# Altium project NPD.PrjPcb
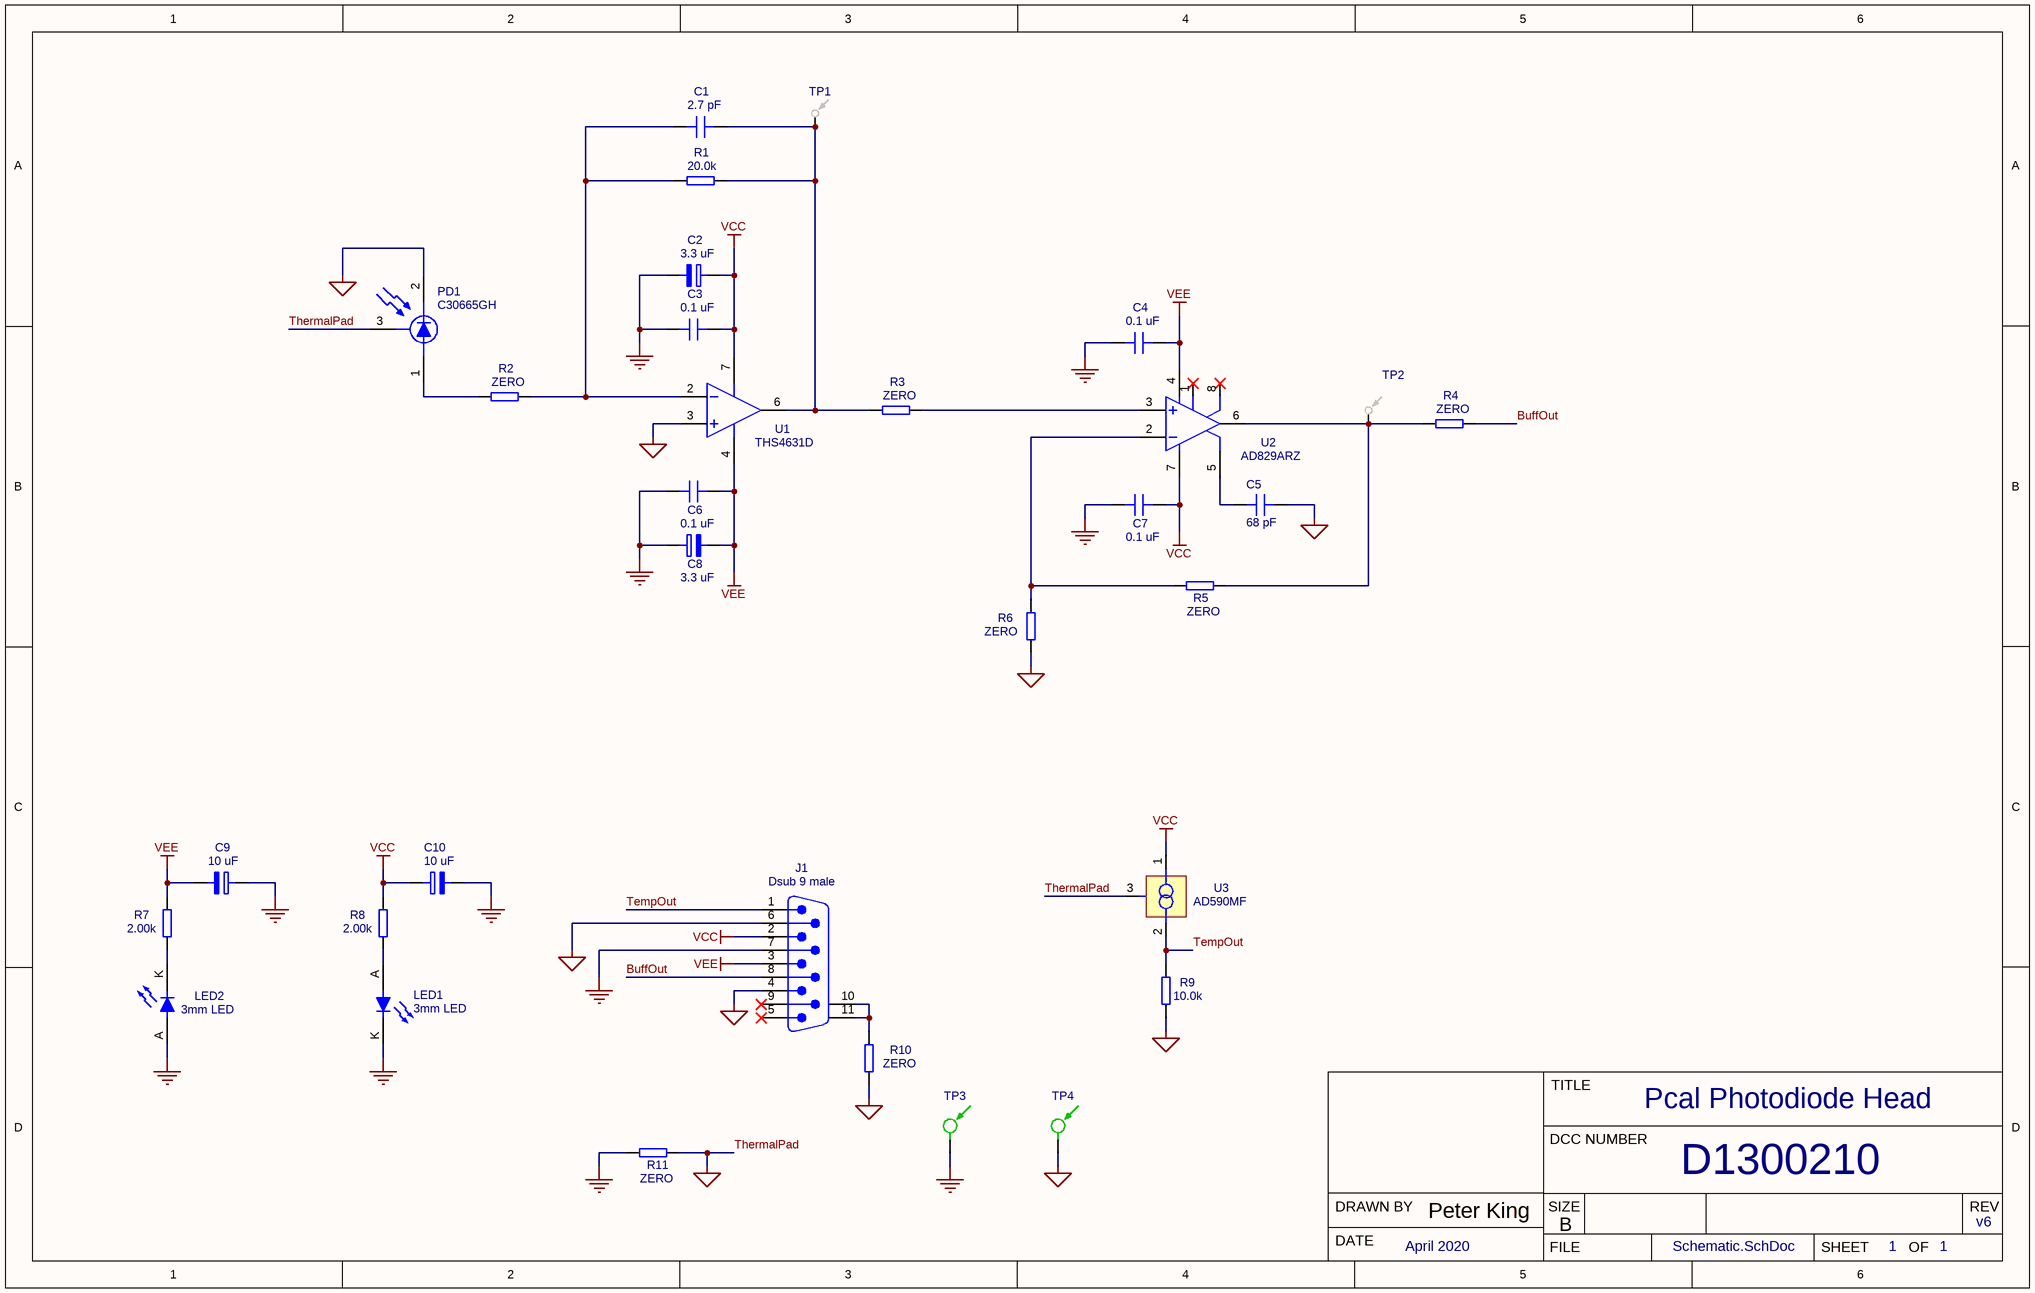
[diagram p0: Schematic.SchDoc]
1 sheet, 32 parts. Net scope: global (net labels, ports and power ports of the same name join across sheets).
Board file: NPD.PcbDoc

## Sheet Schematic.SchDoc
size B; Organization: Altium Limited; Address1: 3 Minna Close; Address2: Belrose; Address3: NSW 2085; Address4: Australia; PageSetup: Record=PageOptions|CenterHorizontal=True|CenterVertical=True|PrintScale=1.12|XCorrection=1.00|YCorrection=1.00|PrintKind=2|BorderSize=5000000|LeftOffset=0|BottomOffset=0|Orientation=2|PaperLength=1000|PaperWidth=1000|Scale=100|PaperSource=15|PrintQuality=600|MediaType=1|DitherType=10|PaperKind=Tabloid|PrintScaleMode=1

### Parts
C1  2.7 pF  [Kemet 0805, low density]
C2  3.3 uF  [Kemet 3528-21]
C3  0.1 uF  [Kemet EIA 1206]
C4  0.1 uF  [0805 low density]
C5  68 pF  [Kemet EIA 0805]
C6  0.1 uF  [Kemet EIA 1206]
C7  0.1 uF  [0805 low density]
C8  3.3 uF  [Kemet 3528-21]
C9  10 uF  [Kemet 6032-28]
C10  10 uF  [Kemet 6032-28]
J1  Dsub 9 male  [1-338309]
LED1  3mm LED  [WP424GDT]
LED2  3mm LED  [WP424GDT]
PD1  C30665GH  [TO-5]
R1  20.0k  [Vishay TNPW0805 e3 low density]
R2  ZERO  [Vishay TNPW0805 e3 low density]
R3  ZERO  [Vishay TNPW0805 e3 low density]
R4  ZERO  [Vishay TNPW0805 e3 low density]
R5  ZERO  [Vishay TNPW0805 e3 low density]
R6  ZERO  [Vishay TNPW0805 e3 low density]
R7  2.00k  [Vishay TNPW0805 e3 low density]
R8  2.00k  [Vishay TNPW0805 e3 low density]
R9  10.0k  [Vishay TNPW0805 e3 low density]
R10  ZERO  [Vishay TNPW0805 e3 low density]
R11  ZERO  [Vishay TNPW0805 e3 low density]
TP1  TEST POINT  [COMPACT TEST POINT]  (value not drawn)
TP2  TEST POINT  [COMPACT TEST POINT]  (value not drawn)
TP3  GROUND TEST POINT  [COMPACT TEST POINT]  (value not drawn)
TP4  GROUND TEST POINT  [COMPACT TEST POINT]  (value not drawn)
U1  THS4631D  [SO-8]
U2  AD829ARZ  [SO-8]
U3  AD590MF  [AD590]

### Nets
PGND: C2.2 C3.1 C4.1 C6.1 C7.1 C8.1 C9.1 C10.2 J1.7 LED1.K(Cathode) LED2.A(Anode) R11.1 TP3.1
ThermalPad: C5.2 J1.4 J1.6 PD1.2(Cathode) PD1.3(Case) R6.1 R9.1 R10.1 R11.2 TP4.1 U1.3(Vin+) U3.3(THERMAL)  [also labelled SGND]
VCC: C2.1 C3.2 C7.2 C10.1 J1.2 R8.2 U1.7(Vs+) U2.7(-Vcc) U3.1(V+)
VEE: C4.2 C6.2 C8.2 C9.2 J1.3 R7.2 U1.4(Vs-) U2.4(-Vcc)
BuffOut: J1.8 R4.2
TempOut: J1.1 R9.2 U3.2(V-)
NetC1_1: C1.1 R1.1 R2.2 U1.2(Vin-)
NetC1_2: C1.2 R1.2 R3.1 TP1.1 U1.6(Vout)
NetC5_1: C5.1 U2.5
NetJ1_10: J1.10 J1.11 R10.2
NetLED1_A: LED1.A(Anode) R8.1
NetLED2_K: LED2.K(Cathode) R7.1
NetPD1_1: PD1.1(Anode) R2.1
NetR3_2: R3.2 U2.3(+In)
NetR4_1: R4.1 R5.2 TP2.1 U2.6(Output)
NetR5_1: R5.1 R6.2 U2.2(-In)

Not connected (* = marked no-connect by the designer): J1 5* 9*; U2 1* 8*

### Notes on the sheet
- TITLE
- Pcal Photodiode Head
- DCC NUMBER
- D1300210
- DRAWN BY
- DATE
- Peter King
- SIZE
- FILE
- B
- SHEET
- OF
- REV
- v6
- April 2020
- Schematic.SchDoc
- 1

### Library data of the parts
C1 = 2.7 pF, 50 V, 0805 ceramic capacitor: 2.7 pF, +/- 0.1 pF C0G ceramic chip capacitor; Manufacturer: Kemet; Manufacturer's Part Number: C0805T279B5GACTU; Rated Voltage: 50 V; Date Added: October 11th, 2016
C2 C8 = 3.3 uF, 35 V, 10% tantalum capacitor: SMD chip tantalum capacitor; Manufacturer: Kemet; Part number: T495B335K035ATE1K0; Date added: 2nd August, 2018; Tolerance: 10%; Voltage DC: 35 VDC; ESR (100kHz): 1000 mOhms
C3 C6 = 0.1 uF, 50 V, 1206 ceramic capacitor: 0.1 uF, +/- 1% U2J ceramic chip capacitor; Manufacturer: Kemet; Manufacturer's Part Number: C1206C104F5JACTU; Rated Voltage: 50 V; Date Added: October 23rd, 2016
C4 C7 = 0.1 uF, 5% 50 V, 0805 ceramic capacitor: 0.1 uF, +/- 5% X7R ceramic chip capacitor; Manufacturer: Kemet; Manufacturer's Part Number: C0805C104J5RACTU; Rated Voltage: 50 V; Date Added: October 23rd, 2016
C5 = 68 pF, 50 V, 0805 ceramic capacitor: 68 pF, +/- 1% C0G ceramic chip capacitor; Manufacturer: Kemet; Manufacturer's Part Number: C0805C680F5GACTU; Rated Voltage: 50 V; Date Added: October 11th, 2016
C9 C10 = 10 uF, 25 V, 10% tantalum capacitor: SMD chip tantalum capacitor; Manufacturer: Kemet; Part number: T495C106K025ATE300; Date added: 2nd August, 2018; Tolerance: 10%; Voltage DC: 25 VDC; ESR (100kHz): 300 mOhms
J1 = Dsub 9 male: Dsub 9 male, vertical; Manufacturer: TE Connectivity; Manufacturer's Part Number: 1-338309-2; Date Added: 18th March, 2020
PD1 = C30665GH: 3 mm InGaAs photodiode; Manufacturer: Excelitas
R1 = 20.0k ohm, +/- 0.05%: 20.0k ohm, +/- 0.05% thin film chip resistor; Manufacturer: KOA Speer; 5 ppm part number: RN732BTTD2002A05; 10 ppm part number: RN732BTTD2002A10; 25 ppm part number: RN732BTTD2002A25; Date added: 15th January, 2017.; Temperature coefficient of resistance: +/- 5 ppm; Power rating: 0.125 W; Temperature coefficient of resistance: +/- 10 ppm; Temperature coefficient of resistance: +/- 25 ppm
R2-R6 R10 R11 = ZERO OHMS: 1206 zero ohm jumper; Manufacturer: Yageo; Part number: RC1206JR-070RL; Vendor 1 part number: 311-0.0ERCT-ND; Date added: 17th January, 2017.; Power rating: 0.125 W; Vendor 1: Digi-Key
R7 R8 = 2.00k ohm, +/- 0.05%: 2.00k ohm, +/- 0.05% thin film chip resistor; Manufacturer: KOA Speer; 5 ppm part number: RN732BTTD2001A05; 10 ppm part number: RN732BTTD2001A10; 25 ppm part number: RN732BTTD2001A25; Date added: 15th January, 2017.; Temperature coefficient of resistance: +/- 5 ppm; Power rating: 0.125 W; Temperature coefficient of resistance: +/- 10 ppm; Temperature coefficient of resistance: +/- 25 ppm
R9 = 10.0k ohm, +/- 0.05%: 10.0k ohm, +/- 0.05% thin film chip resistor; Manufacturer: KOA Speer; 5 ppm part number: RN732BTTD1002A05; 10 ppm part number: RN732BTTD1002A10; 25 ppm part number: RN732BTTD1002A25; Date added: 15th January, 2017.; Temperature coefficient of resistance: +/- 5 ppm; Power rating: 0.125 W; Temperature coefficient of resistance: +/- 10 ppm; Temperature coefficient of resistance: +/- 25 ppm
TP1 TP2 = TP
U1 = THS4631D: high voltage, high slew rate, wideband FET input operational amplifier; Manufacturer: Texas Instruments; Date added: October 22nd, 2018
U2 = AD829ARZ: high speed, low noise video op amp; Manufacturer: Analog Devices; Date added: October 24th, 2018
U3 = AD590MF: 2 terminal IC temperature transducer; Manufacturer: Analog Devices; Date added: December 14th, 2018; Calibration error: +/- 0.5 degC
